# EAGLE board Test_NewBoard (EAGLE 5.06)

Size 66.04 x 57.13 mm. Coordinates in mm from the lower left corner, seen from the top.
Outline: 0,0 31.73,0 31.73,23.8 0,23.8 0,0
Outline: 34.29,0 66.02,0 66.02,23.8 34.29,23.8 34.29,0
Outline: 24.13,25.4 24.13,57.13 0.33,57.13 0.33,25.4 24.13,25.4
Outline: 66.04,53.34 34.31,53.34 34.31,29.54 66.04,29.54 66.04,53.34
Copper layers (1*16): Top 0.035mm / dielectric 1.5mm / Bottom 0.035mm
Design rules "default": minimum track width 10mil, minimum drill 24mil, track to track 10mil, track to pad 8mil, pad to pad 8mil, via to via 10mil, smd to smd 10mil, copper to edge 40mil, drill to drill 8mil, minimum pad ring 10mil, minimum via ring 8mil, stop-mask expansion 4mil, vias tented up to drill 0mil, thermal gap 10mil

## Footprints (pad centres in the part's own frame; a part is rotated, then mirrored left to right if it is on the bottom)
0207/10 = drill 0.813 octagon: 1 -5.08,0; 2 5.08,0

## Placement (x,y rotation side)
R1  1000  [0207/10]  7.62,11.43 270 top
R2  2000  [0207/10]  12.7,11.43 270 top
R3  3000  [0207/10]  17.78,11.43 270 top
R4  4000  [0207/10]  22.86,11.43 270 top
R5  1000  [0207/10]  41.91,11.43 270 top
R6  2000  [0207/10]  46.99,11.43 270 top
R7  3000  [0207/10]  52.07,11.43 270 top
R8  4000  [0207/10]  57.15,11.43 270 top
R9  1000  [0207/10]  12.7,33.02 0 top
R10  2000  [0207/10]  12.7,38.1 0 top
R11  3000  [0207/10]  12.7,43.18 0 top
R12  4000  [0207/10]  12.7,48.26 0 top
R13  1000  [0207/10]  58.42,41.91 90 top
R14  2000  [0207/10]  53.34,41.91 90 top
R15  3000  [0207/10]  48.26,41.91 90 top
R16  4000  [0207/10]  43.18,41.91 90 top

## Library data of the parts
R1-R16 = rcl

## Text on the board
tPlace: Kopie 180° links gedreht | von links nicht lesbar!!! | von oben nicht lesbar!!! | Kopie 90° links gedreht | Original | Kopie Original
_tNames: R4 | R3 | R2 | R4 | R3 | R2 | R1 | R1 | R1 | R2 | R3 | R4 | R1 | R2 | R3 | R4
